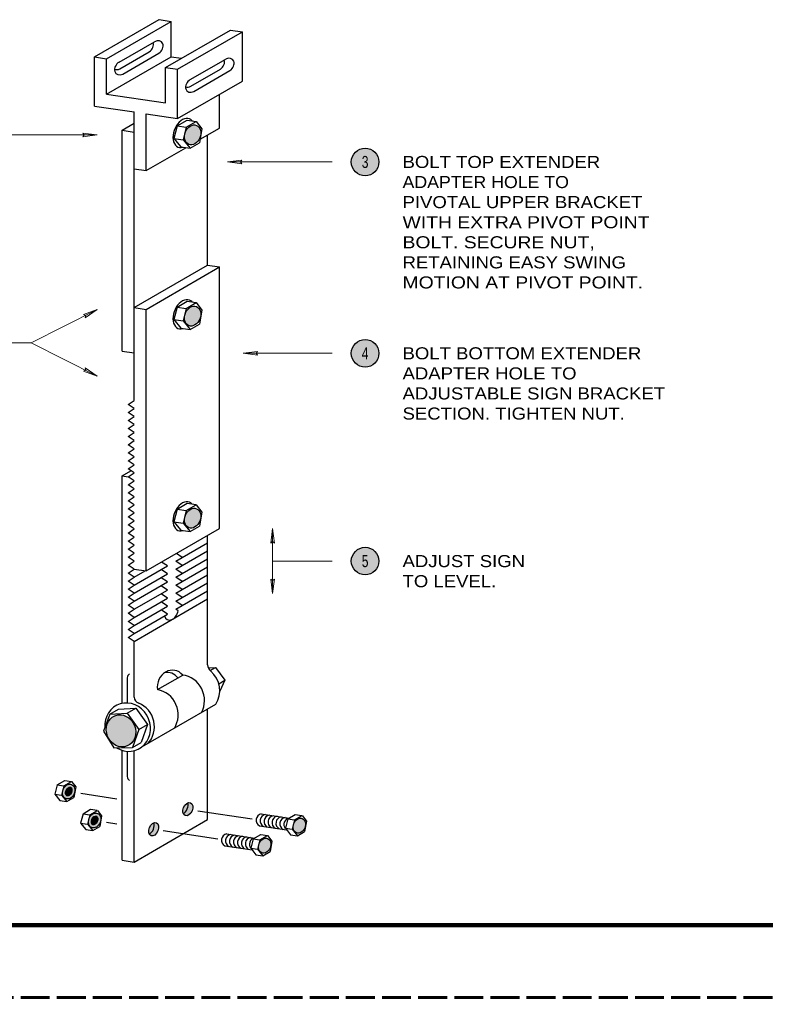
# Model space of a CAD drawing. Extents: x 312583 to 312853, y 144376 to 144586.
# Drawn here: x 312678.9 to 312725.3, y 144418.6 to 144479.5 of the extents above; entities that cross this region are included whole.
import ezdxf
from ezdxf.enums import TextEntityAlignment as Align

# ---------------------------------------------------------------- set-up
doc = ezdxf.new("R2010")
doc.units = 0
doc.header["$LTSCALE"] = 0.3
doc.linetypes.add('LONG_DASHED', pattern=[7.5, 6, -1.5])
for name, color, linetype, lineweight in [('1', 7, 'Continuous', 25), ('2', 7, 'Continuous', 13), ('63', 7, 'LONG_DASHED', 60)]:
    doc.layers.add(name, color=color, linetype=linetype, lineweight=lineweight)

msp = doc.modelspace()

# ---------------------------------------------------------------- hatches: boundary and pattern name
at = {"layer": '1'}
h = msp.add_hatch(color=256, dxfattribs=at)
edge = h.paths.add_edge_path()
edge.add_ellipse((312689.6521, 144472.2869), major_axis=(0.2406, 0.5922), ratio=0.761491, start_angle=0, end_angle=360)
h = msp.add_hatch(color=256, dxfattribs=at)
edge = h.paths.add_edge_path()
edge.add_ellipse((312689.6521, 144461.002), major_axis=(0.2406, 0.5922), ratio=0.761491, start_angle=0, end_angle=360)
h = msp.add_hatch(color=256, dxfattribs=at)
edge = h.paths.add_edge_path()
edge.add_ellipse((312689.6521, 144448.4226), major_axis=(0.2406, 0.5922), ratio=0.761491, start_angle=0, end_angle=360)
h = msp.add_hatch(color=256, dxfattribs=at)
edge = h.paths.add_edge_path()
edge.add_ellipse((312685.1969, 144435.1798), major_axis=(-0.3821, 0.9403), ratio=0.8873452, start_angle=0, end_angle=360)
h = msp.add_hatch(color=256, dxfattribs=at)
edge = h.paths.add_edge_path()
edge.add_ellipse((312681.9384, 144431.4035), major_axis=(0.1805, 0.4441), ratio=0.761491, start_angle=0, end_angle=360)
h = msp.add_hatch(color=256, dxfattribs=at)
edge = h.paths.add_edge_path()
edge.add_ellipse((312681.9384, 144431.4035), major_axis=(0.11, 0.2708), ratio=0.6087617, start_angle=0, end_angle=360)
h = msp.add_hatch(color=256, dxfattribs=at)
edge = h.paths.add_edge_path()
edge.add_ellipse((312689.3555, 144430.3055), major_axis=(0.1639, 0.4034), ratio=0.649846, start_angle=0, end_angle=360)
h = msp.add_hatch(color=256, dxfattribs=at)
edge = h.paths.add_edge_path()
edge.add_ellipse((312683.55, 144429.6026), major_axis=(0.1805, 0.4441), ratio=0.761491, start_angle=0, end_angle=360)
h = msp.add_hatch(color=256, dxfattribs=at)
edge = h.paths.add_edge_path()
edge.add_ellipse((312683.55, 144429.6026), major_axis=(0.11, 0.2708), ratio=0.6087617, start_angle=0, end_angle=360)
h = msp.add_hatch(color=256, dxfattribs=at)
edge = h.paths.add_edge_path()
edge.add_ellipse((312687.2305, 144429.0578), major_axis=(0.1639, 0.4034), ratio=0.649846, start_angle=0, end_angle=360)
h = msp.add_hatch(color=256, dxfattribs=at)
edge = h.paths.add_edge_path()
edge.add_ellipse((312696.2971, 144429.2777), major_axis=(0.1805, 0.4441), ratio=0.761491, start_angle=0, end_angle=360)
h = msp.add_hatch(color=256, dxfattribs=at)
edge = h.paths.add_edge_path()
edge.add_ellipse((312694.1434, 144428.0343), major_axis=(0.1805, 0.4441), ratio=0.761491, start_angle=0, end_angle=360)
at = {"layer": '2'}
for points in [[(312701.2546, 144470.6004, 1), (312699.5354, 144470.6004, 1)], [(312701.2546, 144458.6874, 1), (312699.5354, 144458.6874, 1)], [(312701.2546, 144445.7501, 1), (312699.5354, 144445.7501, 1)]]:
    msp.add_hatch(color=256, dxfattribs=at).paths.add_polyline_path(points)

# ---------------------------------------------------------------- linework, layer by layer
at = {"layer": '1'}
for p, q in [((312683.5463, 144477.1395), (312687.5762, 144479.4662)), ((312684.2963, 144477.0284), (312688.3263, 144479.3552)), ((312687.5762, 144479.4662), (312688.3263, 144479.3552)), ((312688.3263, 144477.1529), (312688.3263, 144479.3552)), ((312687.9724, 144476.484), (312692.0025, 144478.8107)), ((312692.0025, 144478.8107), (312692.7524, 144478.6997)), ((312685.0826, 144476.8143), (312687.2865, 144478.0868)), ((312683.5463, 144474.0762), (312683.5463, 144477.1395)), ((312683.5463, 144477.1395), (312684.2963, 144477.0284)), ((312684.2963, 144474.8262), (312688.3263, 144477.1529)), ((312684.2963, 144474.8262), (312684.2963, 144477.0284)), ((312685.1166, 144476.401), (312686.9546, 144477.4621)), ((312685.3042, 144476.0762), (312687.5516, 144477.3737)), ((312688.3263, 144477.1529), (312688.9668, 144477.0581)), ((312689.5087, 144475.7283), (312691.7127, 144477.0007)), ((312687.9724, 144474.2817), (312687.9724, 144476.484)), ((312688.7224, 144473.3096), (312688.7224, 144476.3729)), ((312689.5428, 144475.315), (312691.3807, 144476.3761)), ((312689.7303, 144474.9902), (312691.9777, 144476.2877)), ((312684.2963, 144474.8262), (312687.9724, 144474.2817)), ((312691.3376, 144472.7088), (312691.3376, 144474.8195)), ((312683.5463, 144474.0762), (312686.0086, 144473.7115)), ((312686.7586, 144470.0651), (312686.7586, 144473.6004)), ((312686.7586, 144473.6004), (312688.7224, 144473.3096)), ((312685.2586, 144472.5762), (312686.0086, 144473.0092)), ((312688.6918, 144472.8505), (312688.4917, 144472.0684)), ((312688.6918, 144472.8505), (312689.3176, 144473.2118)), ((312689.3175, 144473.2118), (312689.8733, 144473.1295)), ((312690.1272, 144472.0099), (312691.3376, 144472.7088)), ((312685.2586, 144472.5762), (312686.0086, 144472.4651)), ((312685.2586, 144458.8262), (312685.2586, 144472.5762)), ((312688.4917, 144472.0684), (312689.0579, 144471.9845)), ((312690.5876, 144464.1791), (312690.5876, 144472.2758)), ((312686.7586, 144470.0651), (312689.2263, 144471.4898)), ((312689.4927, 144471.4504), (312690.0912, 144471.7959)), ((312686.0086, 144470.1762), (312686.7586, 144470.0651)), ((312686.7586, 144461.4243), (312691.3375, 144464.068)), ((312691.3375, 144447.7819), (312691.3375, 144464.068)), ((312688.6918, 144461.5655), (312689.3176, 144461.9268)), ((312689.3175, 144461.9268), (312689.8733, 144461.8445)), ((312686.0086, 144461.5354), (312686.7586, 144461.4243)), ((312686.7586, 144445.1382), (312686.7586, 144461.4243)), ((312688.6918, 144461.5655), (312688.4917, 144460.7834)), ((312688.4917, 144460.7834), (312689.0579, 144460.6996)), ((312689.4927, 144460.1654), (312690.0912, 144460.511)), ((312685.2586, 144458.8262), (312686.0086, 144458.7151)), ((312685.2586, 144451.0548), (312685.8168, 144451.3771)), ((312685.2586, 144436.8913), (312685.2586, 144451.0548)), ((312685.2586, 144451.0548), (312685.6336, 144450.9992)), ((312688.6918, 144448.9862), (312688.4917, 144448.2041)), ((312688.6918, 144448.9862), (312689.3176, 144449.3475)), ((312689.3175, 144449.3475), (312689.8733, 144449.2652)), ((312686.7586, 144445.1382), (312691.3375, 144447.7819)), ((312688.4917, 144448.2041), (312689.0579, 144448.1202)), ((312689.4927, 144447.5861), (312690.0912, 144447.9316)), ((312690.5876, 144439.295), (312690.5876, 144447.3489)), ((312688.6047, 144445.7481), (312690.5876, 144446.893)), ((312688.6047, 144445.2481), (312690.5876, 144446.393)), ((312688.6047, 144444.7481), (312690.5876, 144445.893)), ((312689.0066, 144445.9802), (312688.6401, 144446.2245)), ((312686.0086, 144444.2493), (312688.0881, 144445.4499)), ((312686.0086, 144445.2493), (312686.7586, 144445.1382)), ((312688.0881, 144445.4499), (312687.7216, 144445.6942)), ((312689.0066, 144445.4802), (312688.6047, 144445.7481)), ((312688.6047, 144444.2481), (312690.5876, 144445.393)), ((312686.0086, 144444.7493), (312686.6978, 144445.1472)), ((312686.0086, 144443.7493), (312688.088, 144444.9499)), ((312688.088, 144444.9499), (312687.6861, 144445.2178)), ((312688.088, 144444.4499), (312687.6861, 144444.7178)), ((312689.0066, 144444.9802), (312688.6047, 144445.2481)), ((312688.6047, 144443.7481), (312690.5876, 144444.893)), ((312689.0066, 144444.4802), (312688.6047, 144444.7481)), ((312686.0086, 144443.2493), (312688.088, 144444.4499)), ((312688.088, 144443.9499), (312687.6861, 144444.2178)), ((312688.6047, 144443.2481), (312690.5876, 144444.393)), ((312689.0066, 144443.9802), (312688.6047, 144444.2481)), ((312686.0086, 144442.7493), (312688.088, 144443.9499)), ((312686.0086, 144442.2493), (312688.088, 144443.4499)), ((312688.088, 144443.4499), (312687.6861, 144443.7178)), ((312688.6047, 144442.7481), (312690.5876, 144443.893)), ((312689.0066, 144443.4802), (312688.6047, 144443.7481)), ((312686.0086, 144440.7493), (312690.5876, 144443.393)), ((312686.0086, 144441.7493), (312688.088, 144442.9499)), ((312688.088, 144442.9499), (312687.6861, 144443.2178)), ((312689.0066, 144442.9802), (312688.6047, 144443.2481)), ((312686.0086, 144441.2493), (312688.0881, 144442.4499)), ((312688.0881, 144442.4499), (312687.6861, 144442.7178)), ((312688.7465, 144442.6536), (312688.6047, 144442.7481)), ((312686.0086, 144437.2889), (312686.0086, 144440.7493)), ((312687.4672, 144437.7468), (312689.0353, 144438.6521)), ((312690.6259, 144439.1081), (312691.0841, 144439.131)), ((312690.7445, 144438.935), (312691.0841, 144439.131)), ((312691.0841, 144439.131), (312691.6675, 144438.3305)), ((312685.5884, 144438.4925), (312685.5884, 144436.9169)), ((312691.2822, 144438.1081), (312691.6675, 144438.3305)), ((312691.6675, 144438.3305), (312691.341, 144437.6526)), ((312686.4932, 144434.1844), (312691.0912, 144436.8391)), ((312684.501, 144436.2209), (312685.0381, 144436.531)), ((312685.0381, 144436.531), (312686.1214, 144436.5851)), ((312685.5843, 144436.275), (312686.1214, 144436.5851)), ((312690.5876, 144429.6577), (312690.5876, 144436.5483)), ((312690.5876, 144435.8759), (312690.5876, 144436.5483)), ((312686.3149, 144435.2725), (312686.852, 144435.5826)), ((312685.912, 144434.1421), (312686.4491, 144434.4522)), ((312685.2586, 144427.1251), (312685.2586, 144433.9705)), ((312685.5884, 144433.907), (312685.5884, 144432.3314)), ((312686.0086, 144427.014), (312686.0086, 144433.9449)), ((312681.2181, 144431.8262), (312681.6875, 144432.0972)), ((312681.6875, 144432.0972), (312682.1043, 144432.0354)), ((312681.2181, 144431.8262), (312681.0681, 144431.2396)), ((312682.6857, 144431.2929), (312684.9371, 144430.9596)), ((312681.0681, 144431.2396), (312681.4928, 144431.1767)), ((312681.8189, 144430.7761), (312682.2677, 144431.0353)), ((312682.8297, 144430.0253), (312683.2991, 144430.2963)), ((312683.2991, 144430.2963), (312683.7159, 144430.2345)), ((312689.9814, 144430.2129), (312693.3674, 144429.7117)), ((312682.8297, 144430.0253), (312682.6797, 144429.4387)), ((312682.6797, 144429.4387), (312683.1044, 144429.3758)), ((312684.2973, 144429.492), (312684.9371, 144429.3973)), ((312693.9278, 144430.0077), (312695.6638, 144429.7506)), ((312695.5768, 144429.7004), (312695.4268, 144429.1138)), ((312695.5768, 144429.7004), (312696.0462, 144429.9714)), ((312696.0462, 144429.9714), (312696.463, 144429.9096)), ((312683.4305, 144428.9752), (312683.8793, 144429.2344)), ((312687.8277, 144428.9694), (312691.2137, 144428.4682)), ((312693.8108, 144429.2668), (312695.5067, 144429.0156)), ((312695.4268, 144429.1138), (312695.8515, 144429.0509)), ((312696.1776, 144428.6503), (312696.6264, 144428.9095)), ((312691.7741, 144428.7643), (312693.5101, 144428.5072)), ((312693.4231, 144428.4569), (312693.2731, 144427.8704)), ((312693.4231, 144428.4569), (312693.8925, 144428.7279)), ((312693.8925, 144428.7279), (312694.3093, 144428.6662)), ((312691.6571, 144428.0234), (312693.353, 144427.7722)), ((312693.2731, 144427.8704), (312693.6978, 144427.8075)), ((312694.0239, 144427.4069), (312694.4727, 144427.666))]:
    msp.add_line(p, q, dxfattribs=at)
at = {"layer": '1', "lineweight": 158}
msp.add_line((312616.5, 144423.0846), (312849, 144423.0846), dxfattribs=at)
at = {"layer": '1'}
for points in [[(312687.9724, 144476.484), (312688.7224, 144476.3729), (312692.7524, 144478.6997)], [(312688.7224, 144473.3096), (312692.7524, 144475.6363), (312692.7524, 144478.6997)], [(312686.0086, 144453.7493), (312685.6336, 144453.9993), (312686.0086, 144454.2493), (312685.6336, 144454.4993), (312686.0086, 144454.7493), (312685.6336, 144454.9993), (312686.0086, 144455.2493), (312685.6336, 144455.4993), (312686.0086, 144455.7493), (312686.0086, 144473.7115)], [(312688.6918, 144472.8505), (312689.258, 144472.7666), (312689.8838, 144473.1279)], [(312689.258, 144472.7666), (312689.0579, 144471.9845), (312689.4927, 144471.4504)], [(312689.8838, 144473.1279), (312690.2372, 144472.6654), (312690.0912, 144471.7959)], [(312688.4917, 144472.0684), (312688.9265, 144471.5342), (312689.4927, 144471.4504)], [(312686.0086, 144461.5354), (312690.5876, 144464.1791), (312691.3375, 144464.068)], [(312688.6918, 144461.5655), (312689.258, 144461.4817), (312689.8838, 144461.843)], [(312689.8838, 144461.843), (312690.2372, 144461.3804), (312690.0912, 144460.511)], [(312689.258, 144461.4817), (312689.0579, 144460.6996), (312689.4927, 144460.1654)], [(312688.4917, 144460.7834), (312688.9265, 144460.2493), (312689.4927, 144460.1654)], [(312685.6336, 144447.9993), (312686.0086, 144448.2493), (312685.6336, 144448.4993), (312686.0086, 144448.7493), (312685.6336, 144448.9993), (312686.0086, 144449.2493), (312685.6336, 144449.4993), (312686.0086, 144449.7493), (312685.6336, 144449.9993), (312686.0086, 144450.2493), (312685.6336, 144450.4993), (312686.0086, 144450.7493), (312685.6336, 144450.9993), (312686.0086, 144451.2493), (312685.6336, 144451.4993), (312686.0086, 144451.7493), (312685.6336, 144451.9993), (312686.0086, 144452.2493), (312685.6336, 144452.4993), (312686.0086, 144452.7493), (312685.6336, 144452.9993), (312686.0086, 144453.2493), (312685.6336, 144453.4993), (312686.0086, 144453.7493)], [(312688.6918, 144448.9862), (312689.258, 144448.9023), (312689.8838, 144449.2636)], [(312689.258, 144448.9023), (312689.0579, 144448.1202), (312689.4927, 144447.5861)], [(312689.8838, 144449.2636), (312690.2372, 144448.8011), (312690.0912, 144447.9316)], [(312686.0086, 144440.7493), (312685.6336, 144440.9993), (312686.0086, 144441.2493), (312685.6336, 144441.4993), (312686.0086, 144441.7493), (312685.6336, 144441.9993), (312686.0086, 144442.2493), (312685.6336, 144442.4993), (312686.0086, 144442.7493), (312685.6336, 144442.9993), (312686.0086, 144443.2493), (312685.6336, 144443.4993), (312686.0086, 144443.7493), (312685.6336, 144443.9993), (312686.0086, 144444.2493), (312685.6336, 144444.4993), (312686.0086, 144444.7493), (312685.6336, 144444.9993), (312686.0086, 144445.2493), (312685.6336, 144445.4993), (312686.0086, 144445.7493), (312685.6336, 144445.9993), (312686.0086, 144446.2493), (312685.6336, 144446.4993), (312686.0086, 144446.7493), (312685.6336, 144446.9993), (312686.0086, 144447.2493), (312685.6336, 144447.4993), (312686.0086, 144447.7493), (312685.6336, 144447.9993)], [(312688.4917, 144448.2041), (312688.9265, 144447.6699), (312689.4927, 144447.5861)], [(312684.501, 144436.2209), (312684.1013, 144435.1645), (312684.7402, 144434.1254), (312685.912, 144434.1421)], [(312684.501, 144436.2209), (312685.5843, 144436.275), (312686.3149, 144435.2725), (312685.912, 144434.1421)], [(312686.1214, 144436.5851), (312686.852, 144435.5826), (312686.4491, 144434.4522)], [(312681.2181, 144431.8262), (312681.6428, 144431.7633), (312682.1121, 144432.0343)], [(312682.1121, 144432.0343), (312682.3772, 144431.6874), (312682.2677, 144431.0353)], [(312681.6428, 144431.7633), (312681.4928, 144431.1767), (312681.8189, 144430.7761)], [(312681.0681, 144431.2396), (312681.3942, 144430.839), (312681.8189, 144430.7761)], [(312682.8297, 144430.0253), (312683.2544, 144429.9624), (312683.7237, 144430.2334)], [(312683.7237, 144430.2334), (312683.9888, 144429.8865), (312683.8793, 144429.2344)], [(312682.6797, 144429.4387), (312683.0058, 144429.0381), (312683.4305, 144428.9752)], [(312683.2544, 144429.9624), (312683.1044, 144429.3758), (312683.4305, 144428.9752)], [(312685.2586, 144427.1251), (312686.0086, 144427.014), (312690.5876, 144429.6577)], [(312695.5768, 144429.7004), (312696.0015, 144429.6375), (312696.4708, 144429.9085)], [(312696.0015, 144429.6375), (312695.8515, 144429.0509), (312696.1776, 144428.6503)], [(312696.4708, 144429.9085), (312696.7359, 144429.5616), (312696.6264, 144428.9095)], [(312695.4268, 144429.1138), (312695.7529, 144428.7132), (312696.1776, 144428.6503)], [(312693.4231, 144428.4569), (312693.8478, 144428.3941), (312694.3171, 144428.665)], [(312693.8478, 144428.3941), (312693.6978, 144427.8075), (312694.0239, 144427.4069)], [(312694.3171, 144428.665), (312694.5822, 144428.3181), (312694.4727, 144427.666)], [(312693.2731, 144427.8704), (312693.5992, 144427.4698), (312694.0239, 144427.4069)]]:
    msp.add_lwpolyline(points, dxfattribs=at)
for centre, radius, start, end in [((312691.0853, 144439.2969), 0.4967, 180.22652, 231.68552), ((312686.3889, 144437.2819), 0.3804, 178.94586, 256.44003), ((312694.0027, 144429.6162), 0.3986, 100.84228, 241.21763), ((312694.25, 144429.5795), 0.3986, 100.84228, 241.21763), ((312694.4973, 144429.5429), 0.3986, 100.84228, 241.21763), ((312694.7446, 144429.5063), 0.3986, 100.84228, 241.21763), ((312694.9919, 144429.4697), 0.3986, 100.84228, 241.21763), ((312695.2392, 144429.4331), 0.3986, 100.84228, 241.21763), ((312695.4865, 144429.3965), 0.3986, 100.84228, 241.21763), ((312695.7338, 144429.3599), 0.3986, 100.84228, 218.70473), ((312691.849, 144428.3727), 0.3986, 100.84228, 241.21763), ((312692.0963, 144428.3361), 0.3986, 100.84228, 241.21763), ((312692.3436, 144428.2995), 0.3986, 100.84228, 241.21763), ((312692.5909, 144428.2629), 0.3986, 100.84228, 241.21763), ((312692.8382, 144428.2262), 0.3986, 100.84228, 241.21763), ((312693.0855, 144428.1896), 0.3986, 100.84228, 241.21763), ((312693.3328, 144428.153), 0.3986, 100.84228, 241.21763), ((312693.5851, 144428.1156), 0.3986, 100.84228, 218.17149)]:
    msp.add_arc(centre, radius, start, end, dxfattribs=at)
for centre, major_axis, ratio, start_param, end_param in [((312687.4008, 144477.7189), (0.3145, 0.3553), 0.764015, 4.3716846, 7.4201263), ((312686.8038, 144477.8073), (0.3145, 0.3553), 0.764015, 4.3716846, 5.8725332), ((312691.23, 144476.7213), (0.3145, 0.3553), 0.764015, 4.3716846, 5.8725332), ((312691.827, 144476.6329), (0.3145, 0.3553), 0.764015, 4.3716846, 7.4201263), ((312685.2025, 144476.4503), (0.3145, 0.3553), 0.764015, 1.1518111, 4.2474694), ((312685.015, 144476.7751), (0.3145, 0.3553), 0.764015, 3.4232596, 4.2474694), ((312689.6287, 144475.3642), (0.3145, 0.3553), 0.764015, 1.1518111, 4.2474694), ((312689.4411, 144475.689), (0.3145, 0.3553), 0.764015, 3.4232596, 4.2474694), ((312689.1047, 144472.4021), (-0.357, -0.8786), 0.649846, 2.8294508, 6.7628931), ((312689.1047, 144461.1172), (-0.357, -0.8786), 0.649846, 2.8294508, 6.7628931), ((312689.1047, 144448.5378), (-0.357, -0.8786), 0.649846, 2.8294508, 6.7628931), ((312688.3146, 144442.6281), (0.2131, 0.5244), 0.730674, 2.4110504, 5.0475633), ((312686.022, 144438.5322), (0.4336, 0.0397), 0.649846, 2.238563, 3.141509), ((312688.3602, 144437.9494), (0.1817, 0.9986), 0.887345, 5.6414307, 8.2157378), ((312688.0376, 144437.8073), (0.1817, 0.9986), 0.887345, 5.600291, 6.6323001), ((312688.9701, 144437.1524), (-0.5733, 1.4109), 0.924918, 3.772746, 5.8235033), ((312689.9159, 144437.7581), (-0.5733, 1.4109), 0.924918, 3.6971351, 5.2200889), ((312687.3307, 144436.2565), (-0.5733, 1.4109), 0.924918, 3.7094114, 5.7733759), ((312685.6031, 144435.4111), (-0.5733, 1.4109), 0.924918, 2.2297812, 7.5167148), ((312685.8479, 144435.5106), (-0.5733, 1.4109), 0.924918, 3.5253261, 5.5467497), ((312686.022, 144432.2917), (0.4336, -0.0397), 0.649846, 3.1416763, 4.0446223), ((312689.0686, 144430.4431), (0.1639, 0.4034), 0.649846, 3.6987557, 5.6461557), ((312686.9532, 144429.1688), (0.1639, 0.4034), 0.649846, 3.701042, 5.7298077)]:
    msp.add_ellipse(centre, major_axis=major_axis, ratio=ratio, start_param=start_param, end_param=end_param, dxfattribs=at)
for centre, major_axis, ratio in [((312689.6521, 144472.2869), (0.2406, 0.5922), 0.761491), ((312689.6521, 144461.002), (0.2406, 0.5922), 0.761491), ((312689.6521, 144448.4226), (0.2406, 0.5922), 0.761491), ((312685.1969, 144435.1798), (-0.3821, 0.9403), 0.887345), ((312681.9384, 144431.4035), (0.1805, 0.4441), 0.761491), ((312681.9384, 144431.4035), (0.11, 0.2708), 0.608762), ((312689.3555, 144430.3055), (0.1639, 0.4034), 0.649846), ((312683.55, 144429.6026), (0.1805, 0.4441), 0.761491), ((312683.55, 144429.6026), (0.11, 0.2708), 0.608762), ((312687.2305, 144429.0578), (0.1639, 0.4034), 0.649846), ((312696.2971, 144429.2777), (0.1805, 0.4441), 0.761491), ((312694.1434, 144428.0343), (0.1805, 0.4441), 0.761491)]:
    msp.add_ellipse(centre, major_axis=major_axis, ratio=ratio, dxfattribs=at)
at = {"layer": '2'}
for p, q in [((312677.1936, 144472.2869), (312683.7181, 144472.2869)), ((312691.8239, 144470.6004), (312698.3484, 144470.6004)), ((312683.7181, 144457.2724), (312679.5982, 144459.3425)), ((312692.7933, 144458.6874), (312698.3484, 144458.6874)), ((312694.634, 144445.7501), (312694.634, 144447.776)), ((312694.634, 144445.7501), (312698.3484, 144445.7501)), ((312694.634, 144443.7242), (312694.634, 144445.7501))]:
    msp.add_line(p, q, dxfattribs=at)
for points in [[(312682.8181, 144472.3969), (312683.7181, 144472.2869), (312682.8181, 144472.1669), (312682.9081, 144472.2869)], [(312692.7239, 144470.4904), (312691.8239, 144470.6004), (312692.7239, 144470.7204), (312692.6339, 144470.6004)], [(312682.8645, 144461.1068), (312683.7181, 144461.4126), (312682.9678, 144460.9013), (312682.9943, 144461.0489)], [(312693.6933, 144458.5774), (312692.7933, 144458.6874), (312693.6933, 144458.8074), (312693.6033, 144458.6874)], [(312682.9633, 144457.7748), (312683.7181, 144457.2724), (312682.86, 144457.5693), (312682.9943, 144457.6361)], [(312694.524, 144446.876), (312694.634, 144447.776), (312694.754, 144446.876), (312694.634, 144446.966)], [(312694.744, 144444.6242), (312694.634, 144443.7242), (312694.514, 144444.6242), (312694.634, 144444.5342)]]:
    msp.add_lwpolyline(points, close=True, dxfattribs=at)
msp.add_lwpolyline([(312678.0865, 144459.3425), (312679.5982, 144459.3425), (312683.7181, 144461.4126)], dxfattribs=at)
at = {"layer": '2', "lineweight": 25}
for centre in [(312700.395, 144470.6004), (312700.395, 144458.6874), (312700.395, 144445.7501)]:
    msp.add_circle(centre, 0.8596, dxfattribs=at)
at = {"layer": '63'}
msp.add_line((312851.75, 144418.5846), (312583.526, 144418.5846), dxfattribs=at)

# ---------------------------------------------------------------- texts
at = {"layer": '2', "width": 0.75}
for s, p in [('3', (312700.3949, 144470.2254)), ('4', (312700.3949, 144458.3124)), ('5', (312700.3949, 144445.3751))]:
    msp.add_text(s, height=0.75, dxfattribs=at).set_placement(p, align=Align.CENTER)
at = {"layer": '2'}
for s, width, p in [('BOLT TOP EXTENDER ', 1.15, (312702.7248, 144470.2254)), ('ADAPTER HOLE TO', 1.1, (312702.7248, 144468.9754)), ('PIVOTAL UPPER BRACKET ', 1.15, (312702.7248, 144467.7254)), ('WITH EXTRA PIVOT POINT ', 1.2, (312702.7248, 144466.4754)), ('BOLT. SECURE NUT, ', 1.2, (312702.7248, 144465.2254)), ('RETAINING EASY SWING ', 1.15, (312702.7248, 144463.9754)), ('MOTION AT PIVOT POINT.', 1.2, (312702.7248, 144462.7254)), ('BOLT BOTTOM EXTENDER ', 1.15, (312702.7248, 144458.3124)), ('ADAPTER HOLE TO ', 1.15, (312702.7248, 144457.0624)), ('ADJUSTABLE SIGN BRACKET ', 1.15, (312702.7248, 144455.8124)), ('SECTION. TIGHTEN NUT.', 1.15, (312702.7248, 144454.5624)), ('ADJUST SIGN ', 1.15, (312702.7248, 144445.3751)), ('TO LEVEL.', 1.15, (312702.7248, 144444.1251))]:
    msp.add_text(s, height=0.75, dxfattribs=dict(at, width=width)).set_placement(p)

doc.saveas('drawing.dxf')
